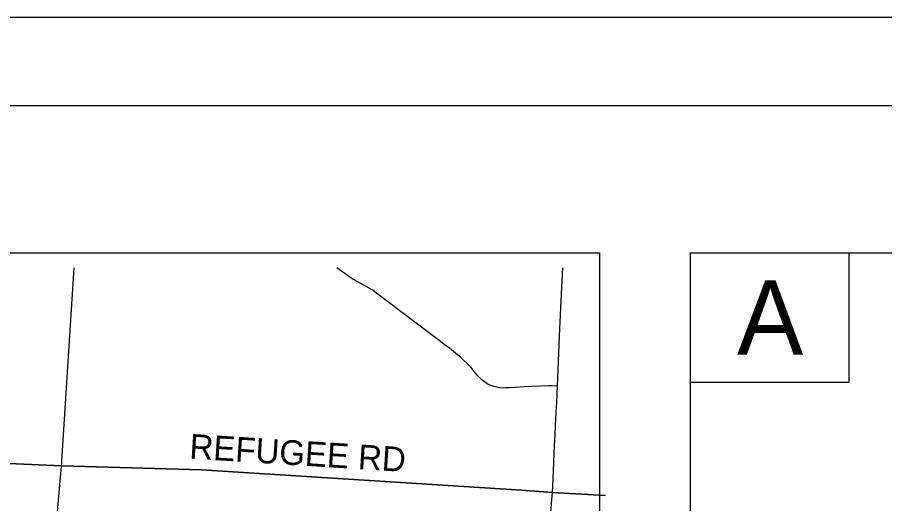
# Model space of a CAD drawing. Extents: x 1880545 to 1948545, y 79309 to 723051.
# Drawn here: x 1921540 to 1931372, y 717538 to 723051 of the extents above; entities that cross this region are included whole.
import ezdxf

# ---------------------------------------------------------------- set-up
doc = ezdxf.new("R2010")
doc.units = 0
for name, color, linetype in [('GM_X_County_Road', 7, 'Continuous'), ('GM_X_Township', 7, 'Continuous'), ('GM_X_Township_Road', 7, 'Continuous'), ('SH_Border', 7, 'Continuous'), ('SH_Cut_Line', 7, 'Continuous'), ('SH_Text', 7, 'Continuous')]:
    doc.layers.add(name, color=color, linetype=linetype)

msp = doc.modelspace()

# ---------------------------------------------------------------- linework, layer by layer
at = {"layer": 'GM_X_County_Road'}
for points in [[(1927604.9, 717661), (1927617, 717901.2), (1927627.1, 718116), (1927636.8, 718323.8), (1927646.1, 718506.6), (1927654.2, 718686.6), (1927664.3, 718871.4), (1927686.8, 719435.9), (1927711.6, 719992.5), (1927723.3, 720211.7)], [(1927522.8, 716724.1), (1927535.4, 716928.2), (1927575.7, 717307.1), (1927591.5, 717482.6), (1927599.2, 717585.3), (1927604.9, 717661)]]:
    msp.add_lwpolyline(points, dxfattribs=at)
at = {"layer": 'GM_X_Township'}
for points in [[(1928206.5, 717628.4), (1927603.7, 717663.8), (1927256.3, 717689.7), (1923628.2, 717922.4), (1922040.5, 717966.3), (1919386.9, 718084.6), (1919532.9, 720211.7)], [(1919386.9, 718084.6), (1922040.5, 717966.3), (1923628.2, 717922.4), (1927256.3, 717689.7), (1927603.7, 717663.8), (1928206.5, 717628.4)]]:
    msp.add_lwpolyline(points, dxfattribs=at)
at = {"layer": 'GM_X_Township_Road'}
for p, q in [((1922041.7, 717963.5), (1922183.3, 720211.7)), ((1928206.5, 717625.6), (1927604.9, 717661))]:
    msp.add_line(p, q, dxfattribs=at)
for points in [[(1927664.3, 718871.4), (1927603.7, 718874.6), (1927563.2, 718874.6), (1927286.6, 718860.9), (1927182.2, 718854.4), (1927118.3, 718851.2), (1927076.3, 718850.4), (1927037.5, 718848.8), (1927007.5, 718849.6), (1926970.3, 718856.9), (1926941.2, 718864.9), (1926907.2, 718876.3), (1926878.9, 718889.2), (1926848.2, 718910.2), (1926811.1, 718939.3), (1926762.1, 718986.6), (1926715.8, 719041), (1926683.1, 719080.1), (1926638.6, 719127.3), (1926603.2, 719160.9), (1926566.8, 719194.5), (1926506.9, 719244.5), (1926460.6, 719280.8), (1926434.2, 719302.6), (1926395.2, 719330.8), (1926321.6, 719387.1), (1926217.2, 719465.2), (1925875.7, 719724.9), (1925626.9, 719912), (1925563.3, 719962.9), (1925322.5, 720093.3), (1925161.3, 720211.7)], [(1922041.7, 717963.5), (1919388.1, 718081.8), (1919382.8, 718082.2)], [(1921820, 713035.6), (1921822.1, 713078.1), (1921852.8, 713690.9), (1921926.2, 714713.5), (1921909, 714875.9), (1921905.1, 714890.2), (1921897.3, 714918.8), (1921858.4, 715008.4), (1921851.9, 715079.8), (1921855.8, 715188.9), (1921903.1, 716422.2), (1922041.7, 717963.5)], [(1927604.9, 717661), (1927257.5, 717686.9), (1923629.4, 717919.6), (1922041.7, 717963.5)]]:
    msp.add_lwpolyline(points, dxfattribs=at)
at = {"layer": 'SH_Border'}
msp.add_lwpolyline([(1883544.6, 722051.2), (1947544.6, 722051.2), (1947544.6, 680051.2), (1883544.6, 680051.2)], close=True, dxfattribs=at)
at = {"layer": 'SH_Cut_Line'}
msp.add_lwpolyline([(1880544.6, 679051.2), (1948544.6, 679051.2), (1948544.6, 723051.2), (1880544.6, 723051.2)], close=True, dxfattribs=at)
at = {"layer": 'SH_Text'}
for points in [[(1884489.7, 720381.4), (1928140.8, 720381.4), (1928140.8, 691152), (1884489.7, 691152)], [(1929171.4, 720381.4), (1943726.4, 720381.4), (1943726.4, 707031.8), (1929171.4, 707031.8)]]:
    msp.add_lwpolyline(points, close=True, dxfattribs=at)
msp.add_lwpolyline([(1929171.4, 718914.5), (1930971.4, 718914.5), (1930971.4, 720381.4)], dxfattribs=at)

# ---------------------------------------------------------------- texts
msp.add_text('A', height=840, dxfattribs=at).set_placement((1929699.9, 719227.9))
msp.add_text('REFUGEE RD', height=280, rotation=356.42938, dxfattribs=at).set_placement((1923485.2, 718049.3))

doc.saveas('drawing.dxf')
